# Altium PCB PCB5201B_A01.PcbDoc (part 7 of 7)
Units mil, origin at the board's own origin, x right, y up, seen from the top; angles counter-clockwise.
Board outline 4527.56 x 2362.2 mil, 6 copper layers (Top Layer, GND Layer 2, Signal Layer 3, Signal Layer 4, VCC Layer 5, Bottom Layer), stack 61.221 mil thick; 361 components, 250 nets, 1223 pads, 1068 vias.
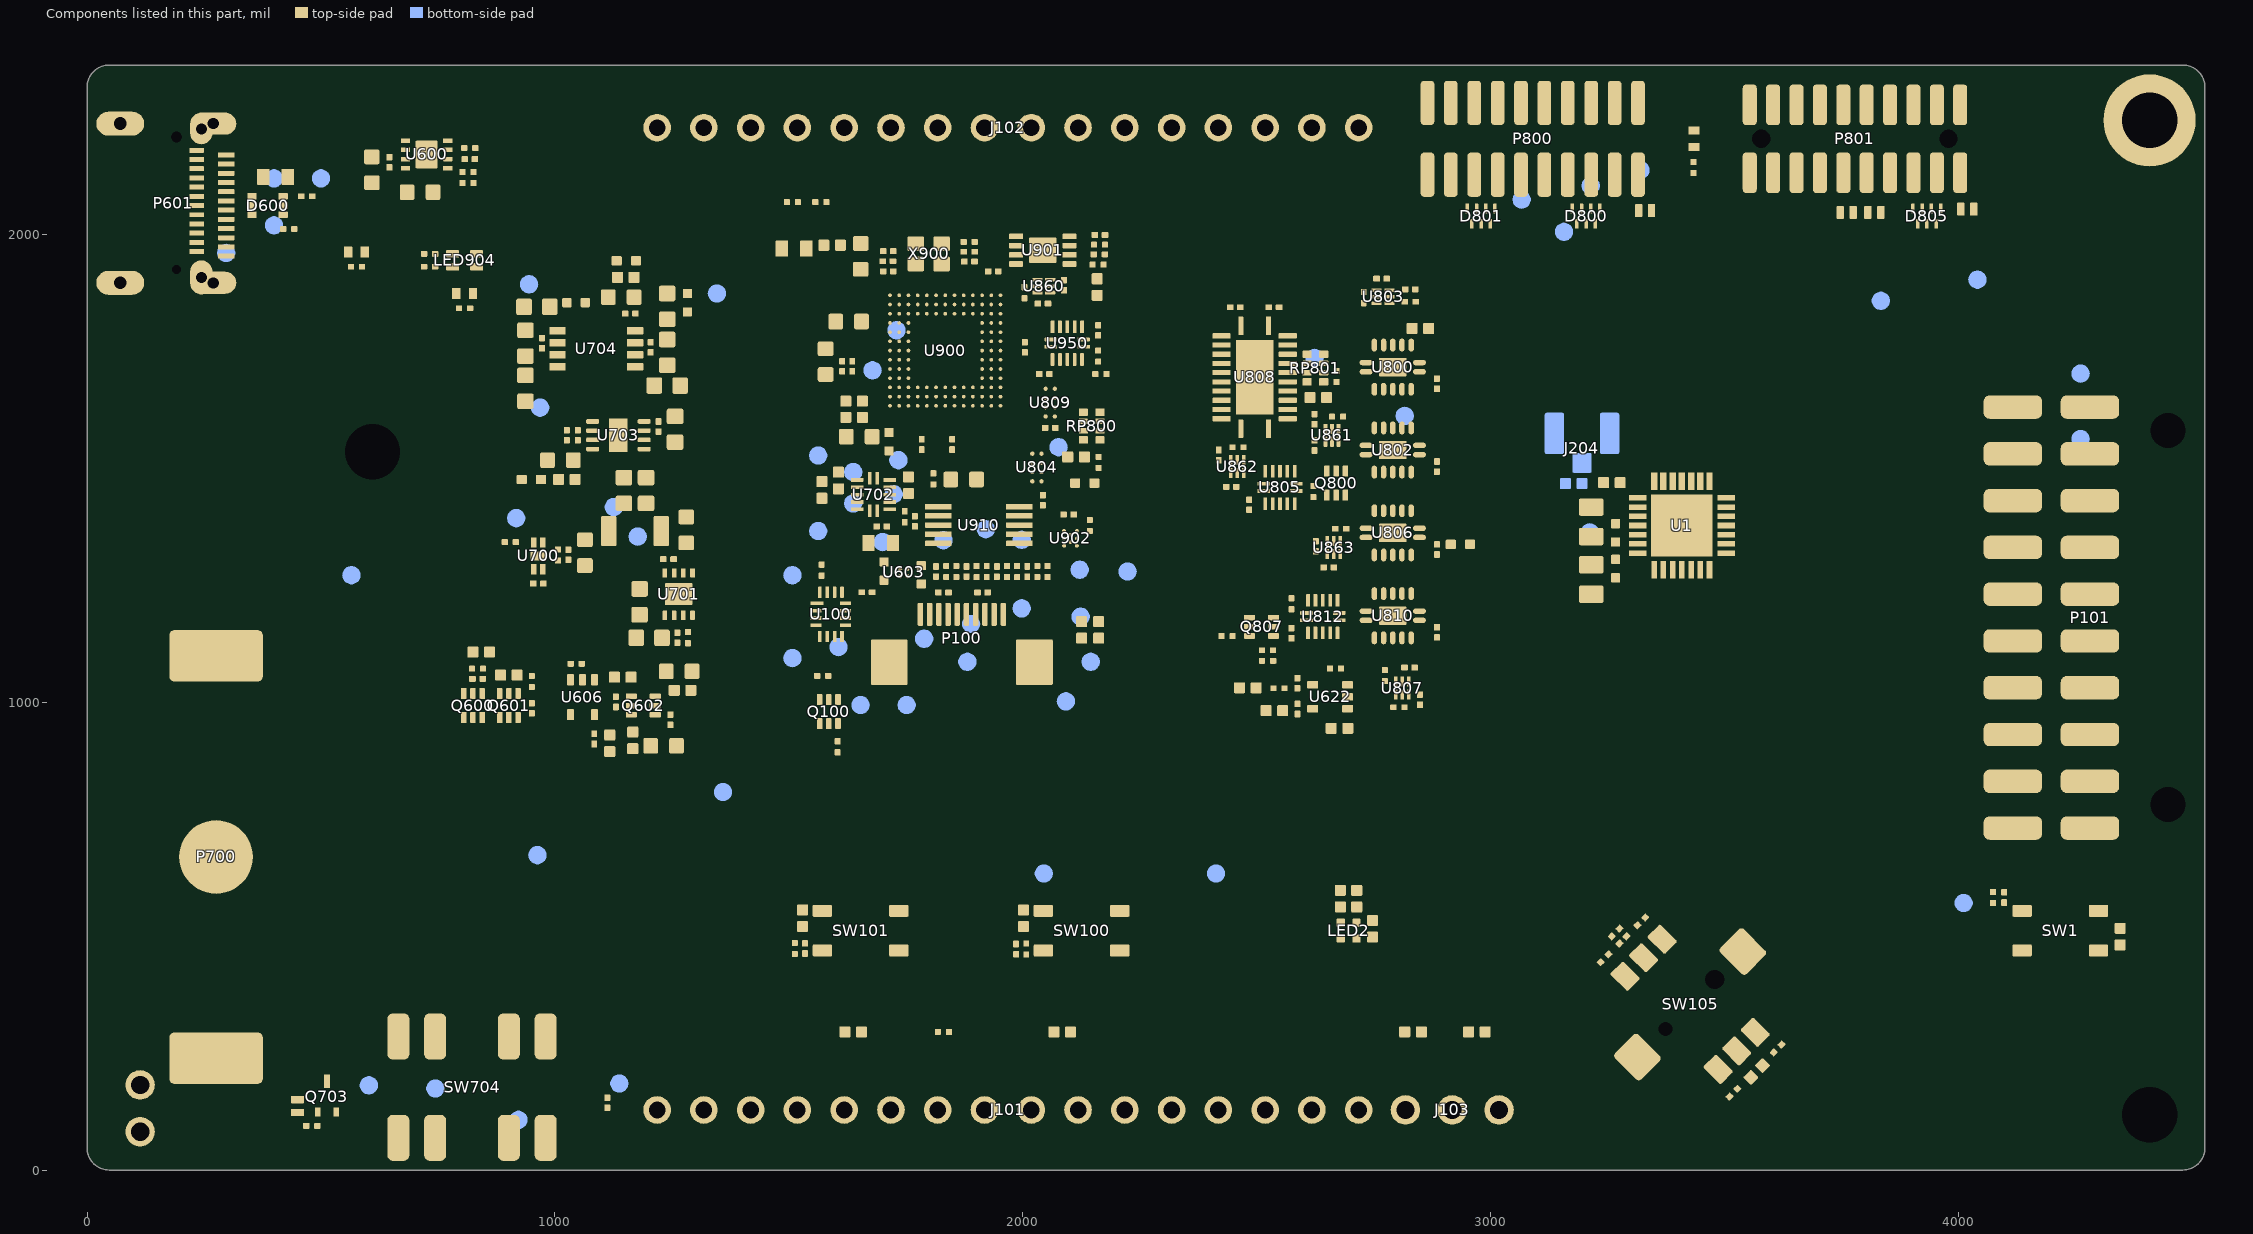
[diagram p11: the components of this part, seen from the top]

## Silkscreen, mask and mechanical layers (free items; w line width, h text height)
Top Overlay:
  lines w7.87: 3354.33,2204.72 3411.42,2204.72 ; 3458.66,2204.72 3515.75,2204.72
  text "1" at 3342.52,2287.4 h59.06
  text "1" at 4035.43,2287.4 h59.06
  text "5V" at 1195.87,2165.35 h47.24 r315
  text "GND" at 1276.57,2165.35 h47.24 r315
  text "P0.0" at 1390.75,2165.35 h47.24 r315
  text "P0.1" at 1493.11,2165.35 h47.24 r315
  text "P0.2" at 1587.6,2165.35 h47.24 r315
  text "P0.3" at 1693.9,2165.35 h47.24 r315
  text "P0.4" at 1796.26,2165.35 h47.24 r315
  text "P0.5" at 1890.75,2165.35 h47.24 r315
  text "P0.6" at 1993.11,2165.35 h47.24 r315
  text "P0.7" at 2091.54,2165.35 h47.24 r315
  text "P1.0" at 2189.96,2165.35 h47.24 r315
  text "P1.2" at 2390.75,2165.35 h47.24 r315
  text "P1.3" at 2491.14,2165.35 h47.24 r315
  text "GND" at 2573.82,2165.35 h47.24 r315
  text "3V3" at 2684.06,2165.35 h47.24 r315
  text "P1.1" at 2286.42,2164.37 h47.24 r315
  text "2" at 4035.43,2090.55 h59.06
  text "2" at 3342.52,2082.68 h59.06
  text "SIMPLICITY" at 3610.24,1927.17 h62.99
  text "DEBUG" at 2959.65,1913.39 h62.99
  text "EXP" at 4053.03,1728.35 h78.74
  text "EFM8" at 3134.06,1695.67 h212.6
  text "20" at 4092.4,1665.35 h59.06
  text "19" at 4245.95,1665.35 h59.06
  text "Busy Bee" at 3133.86,1598.59 h125.98
  text "EFM8BB2" at 3241.38,1126.98 h82.68
  text "2" at 4108.15,653.54 h59.06
  text "1" at 4273.5,653.54 h59.06
  text "LED0" at 2618.11,417.32 h78.74
  text "BTN1" at 1574.8,377.95 h78.74
  text "BTN0" at 2047.24,377.95 h78.74
  text "RESET" at 4110.39,378.83 h78.74
  text "BAT" at 645.67,354.33 h78.74
  text "AEM" at 866.14,354.33 h78.74
  text "C2CK" at 2844.49,255.91 h47.24 r315
  text "VMCU" at 1139.76,253.94 h47.24 r315
  text "GND" at 1257.87,231.3 h47.24 r315
  text "GND" at 2564.96,226.38 h47.24 r315
  text "C2D" at 2766.73,226.38 h47.24 r315
  text "RST" at 2959.65,226.38 h47.24 r315
  text "P3.0" at 1562.01,224.41 h47.24 r315
  text "P3.1" at 1671.26,224.41 h47.24 r315
  text "P2.3" at 1784.45,224.41 h47.24 r315
  text "P2.2" at 1879.92,224.41 h47.24 r315
  text "P2.1" at 1967.52,224.41 h47.24 r315
  text "P2.0" at 2076.77,224.41 h47.24 r315
  text "P1.7" at 2181.1,224.41 h47.24 r315
  text "P1.6" at 2278.54,224.41 h47.24 r315
  text "P1.5" at 2376.97,224.41 h47.24 r315
  text "P1.4" at 2480.31,224.41 h47.24 r315
  text "3V3" at 2670.28,221.46 h47.24 r315
  text "NC" at 1378.91,210.42 h47.24 r315
  text "NC" at 1475.72,210.43 h47.24 r315
Bottom Overlay:
  text "PCB5201B Rev A01" at 51.97,1350.01 h39.37 r90
  text "SPI_CS" at 4438.98,1111.24 h66.93
  text "SPI_SCK" at 4482.28,1012.82 h66.93
  text "SPI_MISO" at 4505.91,912.42 h66.93
  text "SPI_MOSI" at 4502.95,831.71 h66.93
  text "BOARD INFO" at 779.53,621.06 h60
  text "BAT" at 291.34,161.42 h60
  text "GND" at 293.31,57.09 h60
Top Solder:
  lines w31.5: 334.65,-94.49 47.24,-94.49 cw(c47.24,47.24) -94.49,47.24 -94.49,2314.96 cw(c47.24,2314.96) 47.24,2456.69 334.65,2456.69 ; 610.24,-94.49 2224.41,-94.49 ; 610.24,2456.69 2224.41,2456.69 ; 2500,-94.49 3720.47,-94.49 ; 2500,2456.69 3720.47,2456.69 ; 3996.06,-94.49 4480.32,-94.49 ccw(c4480.32,47.24) 4622.05,47.24 4622.05,2314.96 ccw(c4480.32,2314.96) 4480.32,2456.69 3996.06,2456.69 ; 0,47.24 ccw(c47.24,47.24) 47.24,0 4480.32,0 ccw(c4480.32,47.24) 4527.56,47.24 4527.56,2314.96 ccw(c4480.32,2314.96) 4480.32,2362.2 47.24,2362.2 ccw(c47.24,2314.96) 0,2314.96 0,47.24
Bottom Solder:
  lines w31.5: 334.65,-94.49 47.24,-94.49 cw(c47.24,47.24) -94.49,47.24 -94.49,2314.96 cw(c47.24,2314.96) 47.24,2456.69 334.65,2456.69 ; 610.24,-94.49 2224.41,-94.49 ; 610.24,2456.69 2224.41,2456.69 ; 2500,-94.49 3720.47,-94.49 ; 2500,2456.69 3720.47,2456.69 ; 3996.06,-94.49 4480.32,-94.49 ccw(c4480.32,47.24) 4622.05,47.24 4622.05,2314.96 ccw(c4480.32,2314.96) 4480.32,2456.69 3996.06,2456.69 ; 0,47.24 ccw(c47.24,47.24) 47.24,0 4480.32,0 ccw(c4480.32,47.24) 4527.56,47.24 4527.56,2314.96 ccw(c4480.32,2314.96) 4480.32,2362.2 47.24,2362.2 ccw(c47.24,2314.96) 0,2314.96 0,47.24
Board Outline:
  lines w3.94: 0,47.24 ccw(c47.24,47.24) 47.24,0 ; 0,47.24 ccw(c47.24,47.24) 47.24,0 ; 0,47.24 0,2314.96 ; 0,47.24 0,2314.96 ; 0,2314.96 cw(c47.24,2314.96) 47.24,2362.2 ; 0,2314.96 cw(c47.24,2314.96) 47.24,2362.2 ; 47.24,0 4480.32,0 ; 47.24,0 4480.32,0 ; 47.24,2362.2 4480.32,2362.2 ; 47.24,2362.2 4480.32,2362.2 ; 4480.32,0 ccw(c4480.32,47.24) 4527.56,47.24 ; 4480.32,0 ccw(c4480.32,47.24) 4527.56,47.24 ; 4480.32,2362.2 cw(c4480.32,2314.96) 4527.56,2314.96 ; 4480.32,2362.2 cw(c4480.32,2314.96) 4527.56,2314.96 ; 4527.56,47.24 4527.56,2314.96 ; 4527.56,47.24 4527.56,2314.96
Route Tool Path:
  lines w3.94: 334.65,0 47.24,0 cw(c47.24,47.24) 0,47.24 0,2314.96 cw(c47.24,2314.96) 47.24,2362.2 334.65,2362.2 ; 610.24,0 2224.41,0 ; 610.24,2362.2 2224.41,2362.2 ; 2500,0 3720.47,0 ; 2500,2362.2 3720.47,2362.2 ; 3996.06,0 4480.32,0 ccw(c4480.32,47.24) 4527.56,47.24 4527.56,2314.96 ccw(c4480.32,2314.96) 4480.32,2362.2 3996.06,2362.2 ; -94.49,47.24 ccw(c47.24,47.24) 47.24,-94.49 ; -94.49,47.24 ccw(c47.24,47.24) 47.24,-94.49 ; -94.49,47.24 -94.49,2314.96 ; -94.49,47.24 -94.49,2314.96 ; -94.49,2314.96 cw(c47.24,2314.96) 47.24,2456.69 ; 47.24,-94.49 334.65,-94.49 47.24,-94.49 ; 47.24,2456.69 334.65,2456.69 47.24,2456.69 ; 4480.32,-94.49 ccw(c4480.32,47.24) 4622.05,47.24 ; 4480.32,-94.49 ccw(c4480.32,47.24) 4622.05,47.24 ; 4480.32,-94.49 3996.06,-94.49 4480.32,-94.49 ; 4480.32,2456.69 cw(c4480.32,2314.96) 4622.05,2314.96 ; 4480.32,2456.69 cw(c4480.32,2314.96) 4622.05,2314.96 ; 4480.32,2456.69 3996.06,2456.69 4480.32,2456.69 ; 4622.05,47.24 4622.05,2314.96 ; 4622.05,47.24 4622.05,2314.96 ; 610.24,-94.49 2224.41,-94.49 610.24,-94.49 ; 610.24,2456.69 2224.41,2456.69 610.24,2456.69 ; 2500,-94.49 3720.47,-94.49 2500,-94.49 ; 2500,2456.69 3720.47,2456.69 2500,2456.69
Top Component Center (Mech19):
  the board outline again, w3.94
Bottom Component Center:
  the board outline again, w3.94
Assembly Drawing Frame (Top):
  lines w7.87: -2954.94,-1609.25 -2890.96,-1609.25 ; -2954.94,228.35 -2890.96,228.35 ; -2954.94,2065.94 -2890.96,2065.94 ; -803.37,-3508.86 -803.37,-3445.87 ; -803.37,3904.53 -803.37,3967.52 ; 1284.23,-3508.86 1284.23,-3445.87 ; 1284.23,3904.53 1284.23,3967.52 ; 3371.83,-3508.86 3371.83,-3445.87 ; 3371.83,3904.53 3371.83,3967.52 ; 5459.43,-3508.86 5459.43,-3445.87 ; 5459.43,3904.53 5459.43,3967.52 ; 7547.03,-1608.27 7611,-1608.27 ; 7547.03,229.33 7611,229.33 ; 7547.03,2066.93 7611,2066.93 ; 7611,-3508.86 -2954.94,-3508.86 -2954.94,3967.52 7611,3967.52 7611,-3507.87 ; -2890.96,-3445.87 -2890.96,3904.53 7547.03,3904.53 7547.03,-3445.87 -2890.96,-3445.87
  text "5" at -1893.03,3929.3 h19.68
  text "1" at 6599.37,3928.9 h19.68
  text "2" at 4401.63,3928.72 h19.68
  text "4" at 219.76,3924.96 h19.68
  text "3" at 2384.65,3924.96 h19.68
  text "D" at 7575.2,2981.65 h19.68
  text "D" at -2929.21,2976.93 h19.68
  text "C" at 7571.57,1156.22 h19.68
  text "C" at -2932.05,1153.54 h19.68
  text "B" at 7578.82,-680.08 h19.68
  text "B" at -2925.75,-710.55 h19.68
  text "A" at 7575.2,-2477.13 h19.68
  text "A" at -2930.31,-2517.8 h19.68
  text "3" at 2400.15,-3484.89 h19.68
  text "4" at 318.19,-3485.96 h19.68
  text "2" at 4440.96,-3485.86 h19.68
  text "1" at 6602.44,-3487.8 h19.68
  text "5" at -1894.8,-3488.98 h19.68
Title Block (Top):
  drawing of 27 lines, arcs and shapes, not listed
  text "Board Title" at 4806.87,-2463.58 h98.43
  text "EFM8BB2 Busy Bee STK" at 4861.99,-2682.09 h137.8
  text "Page Title" at 4806.87,-2846.46 h98.43
  text "Designed:" at 3537.19,-2994.09 h66.93
  text "Approved:" at 4174.98,-2994.09 h66.93
  text "Top Assembly" at 4861.99,-3000 h125.98
  text "YVB" at 3597.22,-3092.52 h86.61
  text "DDC" at 4229.11,-3092.52 h86.61
  text "Revision" at 7086.4,-3123.03 h66.93
  text "Document number" at 4806.87,-3133.86 h92.52
  text "Size" at 3537.19,-3181.1 h66.93
  text "Sheet Modified Date" at 3731.08,-3181.1 h66.93
  text "A01" at 7097.22,-3243.11 h106.3
  text "BRD5201B (PCB5201B Rev A01)" at 4861.99,-3247.05 h125.98
  text "A4" at 3559.82,-3253.94 h78.74
  text "'.Print_Date'" at 3753.72,-3253.94 h78.74
  text "Sheet" at 7086.4,-3346.46 h66.93
  text "COPYRIGHT SILICON LABORATORIES  INC. 2022" at 3720.16,-3386.14 h66.93
  text "CONFIDENTIAL -SUBJECT TO TERMS OF USE" at 5294.25,-3386.14 h66.93
  text "1" at 7133.64,-3423.23 h66.93
  text "of" at 7256.67,-3423.23 h66.93
  text "2" at 7363.96,-3423.23 h66.93
Assembly Drawing Frame (Bottom):
  lines w7.87: -2954.94,-1609.25 -2890.96,-1609.25 ; -2954.94,228.35 -2890.96,228.35 ; -2954.94,2065.94 -2890.96,2065.94 ; -803.37,-3508.86 -803.37,-3445.87 ; -803.37,3904.53 -803.37,3967.52 ; 1284.23,-3508.86 1284.23,-3445.87 ; 1284.23,3904.53 1284.23,3967.52 ; 3371.83,-3508.86 3371.83,-3445.87 ; 3371.83,3904.53 3371.83,3967.52 ; 5459.43,-3508.86 5459.43,-3445.87 ; 5459.43,3904.53 5459.43,3967.52 ; 7547.03,-1608.27 7611,-1608.27 ; 7547.03,229.33 7611,229.33 ; 7547.03,2066.93 7611,2066.93 ; 7611,-3508.86 -2954.94,-3508.86 -2954.94,3967.52 7611,3967.52 7611,-3507.87 ; -2890.96,-3445.87 -2890.96,3904.53 7547.03,3904.53 7547.03,-3445.87 -2890.96,-3445.87
  text "5" at -1877.31,3931.64 h19.68
  text "2" at 4415.22,3929.31 h19.68
  text "1" at 6605.52,3929.07 h19.68
  text "4" at 234.19,3926.48 h19.68
  text "3" at 2398.44,3925.26 h19.68
  text "D" at 7586.74,2983.05 h19.68
  text "D" at -2915.75,2975.35 h19.68
  text "D" at -2915.75,2975.35 h19.68
  text "C" at -2919.91,1156.12 h19.68
  text "C" at 7584.37,1156.04 h19.68
  text "B" at 7590.43,-679.74 h19.68
  text "B" at -2914.25,-709.29 h19.68
  text "A" at 7587.32,-2476.85 h19.68
  text "A" at -2917.12,-2517.02 h19.68
  text "3" at 2413.41,-3483.92 h19.68
  text "4" at 330.09,-3486.75 h19.68
  text "2" at 4455,-3486.16 h19.68
  text "1" at 6609.77,-3487.23 h19.68
  text "5" at -1880.94,-3489.17 h19.68
Title Block (Bottom):
  drawing of 27 lines, arcs and shapes, not listed
  text "Board Title" at -150.81,-2463.58 h98.43
  text "EFM8BB2 Busy Bee STK" at -205.93,-2682.09 h137.8
  text "Page Title" at -150.81,-2846.46 h98.43
  text "Approved:" at 481.08,-2994.09 h66.93
  text "Designed:" at 1118.88,-2994.09 h66.93
  text "Bottom Assembly" at -205.93,-3000 h125.98
  text "DDC" at 426.95,-3092.52 h86.61
  text "YVB" at 1058.84,-3092.52 h86.61
  text "Revision" at -2430.33,-3123.03 h66.93
  text "Document number" at -150.81,-3133.86 h92.52
  text "Sheet Modified Date" at 924.98,-3181.1 h66.93
  text "Size" at 1118.88,-3181.1 h66.93
  text "A01" at -2440.73,-3243.11 h106.3
  text "BRD5201B (PCB5201B Rev A01)" at -205.93,-3247.05 h125.98
  text "'.Print_Date'" at 902.34,-3253.94 h78.74
  text "A4" at 1096.24,-3253.94 h78.74
  text "Sheet" at -2430.33,-3346.46 h66.93
  text "COPYRIGHT SILICON LABORATORIES  INC. 2022" at 931.42,-3383.31 h66.93
  text "CONFIDENTIAL -SUBJECT TO TERMS OF USE" at -665.59,-3386.77 h66.93
  text "2" at -2707.89,-3423.23 h66.93
  text "of" at -2600.61,-3423.23 h66.93
  text "2" at -2477.58,-3423.23 h66.93
Assembly Drawing Frame:
  lines w7.87: -3252.68,-3711.52 7908.74,-3711.52 7908.74,4181.2 -3252.68,4181.2 -3252.68,-3711.52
